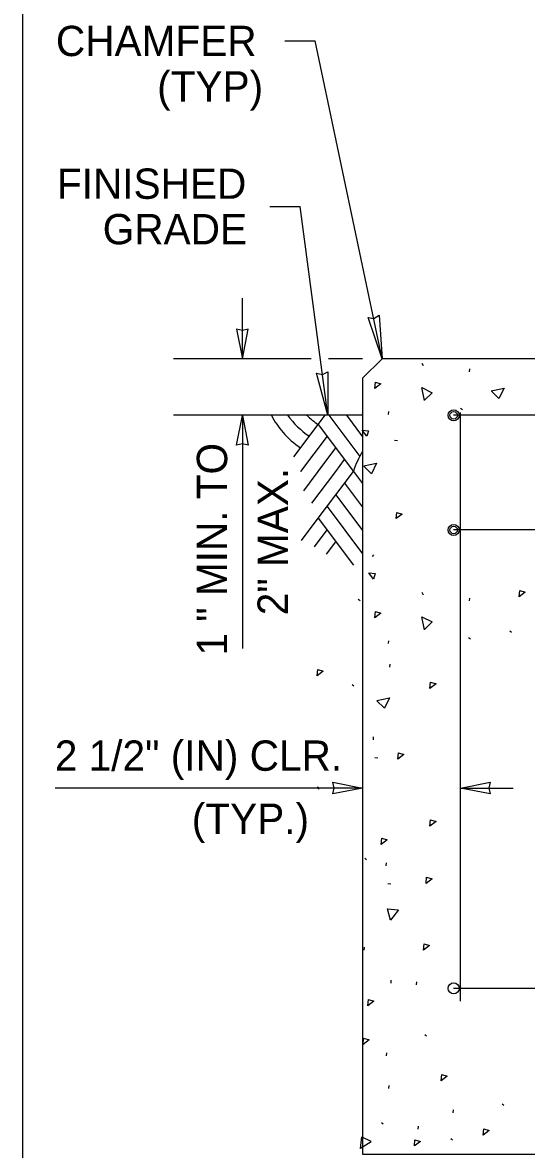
# Model space of a CAD drawing. Extents: x 99862 to 103680, y 99470 to 105076.
# Drawn here: x 99862 to 100128, y 100722 to 101317 of the extents above; entities that cross this region are included whole.
import ezdxf

# ---------------------------------------------------------------- set-up
doc = ezdxf.new("R2010")
doc.units = 0
for name, color, linetype in [('Level 1', 7, 'Continuous'), ('Level 15', 7, 'Continuous'), ('Level 19', 7, 'Continuous'), ('Level 20', 7, 'Continuous'), ('Level 25', 7, 'Continuous'), ('Level 9', 7, 'Continuous')]:
    doc.layers.add(name, color=color, linetype=linetype)

msp = doc.modelspace()

# ---------------------------------------------------------------- linework, layer by layer
at = {"layer": 'Level 1'}
for p, q in [((100051.48, 101139.41), (100041.23, 101129.16)), ((100141.41, 101139.4), (100051.47, 101139.4))]:
    msp.add_line(p, q, dxfattribs=at)
msp.add_lwpolyline([(99862, 99999.5), (103151, 99999.5), (103151, 102075.5), (99862, 102075.5)], close=True, dxfattribs=at)
for points in [[(100041.23, 101129.16), (100041.23, 100934.7)], [(100041.23, 100934.7), (100041.23, 100719.67), (100206.34, 100719.67), (100206.38, 100719.67), (100401.73, 100719.67), (100401.73, 101024.26)]]:
    msp.add_lwpolyline(points, dxfattribs=at)
at = {"layer": 'Level 15'}
for p, q in [((100000.16, 101307.15), (100016.16, 101307.15)), ((100051.47, 101139.4), (100016.16, 101307.15)), ((99992.31, 101219.84), (100008.31, 101219.84)), ((100022.85, 101109.61), (100008.31, 101219.84)), ((99977.84, 101139.4), (99977.84, 101171.4)), ((99995.48, 101109.61), (99958.8, 101109.61)), ((99977.84, 101109.6), (99977.84, 100986.55)), ((100041.23, 100912.91), (99879.13, 100912.91)), ((100092.73, 100912.91), (100120.59, 100912.91))]:
    msp.add_line(p, q, dxfattribs=at)
for points in [[(100051.47, 101139.4), (100044.09, 101161.21), (100047.22, 101160.76), (100049.94, 101162.38)], [(99977.84, 101139.4), (99980.92, 101155.13), (99977.84, 101154.4), (99974.75, 101155.13)], [(100022.85, 101109.61), (100016.95, 101131.86), (100020.04, 101131.2), (100022.87, 101132.63)], [(99977.84, 101109.6), (99980.92, 101093.87), (99977.84, 101094.6), (99974.75, 101093.87)], [(100041.23, 100912.91), (100025.51, 100909.83), (100026.24, 100912.91), (100025.51, 100916)], [(100092.78, 100912.91), (100108.5, 100916), (100107.78, 100912.91), (100108.5, 100909.83)]]:
    msp.add_lwpolyline(points, close=True, dxfattribs=at)
at = {"layer": 'Level 19'}
for p, q in [((100072.45, 101137.17), (100073.09, 101135.87)), ((100097.56, 101132.6), (100097.66, 101134.18)), ((100054.9, 101110.09), (100055.01, 101111.67)), ((100092.86, 101113.35), (100093.79, 101112.67)), ((100058.12, 101096.44), (100059.69, 101096.33)), ((100046.99, 101036.05), (100046.3, 101035.11)), ((100072.45, 101016.21), (100073.09, 101014.91)), ((100038.96, 101012.63), (100039.89, 101011.94)), ((100097.56, 101011.64), (100097.66, 101013.21)), ((100097.09, 100992.39), (100098.02, 100991.71)), ((100118.75, 100995.94), (100119.68, 100995.26)), ((100054.9, 100989.13), (100055.01, 100990.7)), ((100055.61, 100976.66), (100055.72, 100978.24)), ((100035.65, 100967.64), (100036.58, 100966.95)), ((100046.92, 100938.37), (100047.03, 100939.94)), ((100047.7, 100929.02), (100049.28, 100928.91)), ((100017.4, 100913.69), (100018.04, 100912.4)), ((100042.37, 100875.91), (100043.3, 100875.23)), ((100053.68, 100871.89), (100053.79, 100873.46)), ((100054.46, 100862.55), (100056.04, 100862.44)), ((100042.09, 100827.47), (100042.2, 100829.04)), ((100056.22, 100809.97), (100056.33, 100811.54)), ((100069.63, 100809.16), (100069.74, 100810.73)), ((100073.94, 100782.82), (100074.87, 100782.14)), ((100053.79, 100771.68), (100053.91, 100773.26)), ((100055.12, 100754.33), (100055.23, 100755.91)), ((100089.01, 100741.6), (100089.12, 100743.17)), ((100114.8, 100746.35), (100115.73, 100745.66)), ((100051.2, 100736.48), (100052.13, 100735.79)), ((100070.58, 100732.87), (100070.69, 100734.45)), ((100087.69, 100728.05), (100088.62, 100727.36))]:
    msp.add_line(p, q, dxfattribs=at)
for points in [[(100047.72, 101123.76), (100048.04, 101127.07), (100050.92, 101126.2), (100047.72, 101123.76)], [(100073.81, 101117.45), (100072.36, 101124.22), (100077.92, 101121.52), (100073.9, 101117.52)], [(100109.03, 101122.5), (100115.81, 101123.96), (100113.11, 101118.4), (100109.11, 101122.41)], [(100041.03, 101101.77), (100044.34, 101101.44), (100043.47, 101098.57), (100041.03, 101101.77)], [(100041.8, 101082.92), (100048.57, 101084.37), (100045.87, 101078.81), (100041.87, 101082.83)], [(100058.92, 101055.08), (100059.25, 101058.39), (100062.12, 101057.52), (100058.92, 101055.08)], [(100044.48, 101026.42), (100047.79, 101026.09), (100046.92, 101023.22), (100044.48, 101026.42)], [(100123.78, 101013.8), (100124.11, 101017.12), (100126.98, 101016.24), (100123.78, 101013.8)], [(100047.72, 101002.79), (100048.04, 101006.11), (100050.92, 101005.24), (100047.72, 101002.79)], [(100073.81, 100996.48), (100072.36, 101003.26), (100077.92, 101000.56), (100073.9, 100996.56)], [(100017.3, 100972.14), (100017.63, 100975.46), (100020.5, 100974.59), (100017.3, 100972.14)], [(100076.74, 100965.4), (100077.07, 100968.72), (100079.94, 100967.85), (100076.74, 100965.4)], [(100048.69, 100959.11), (100055.46, 100960.56), (100052.76, 100955), (100048.77, 100959.02)], [(100059.76, 100928.13), (100060.08, 100931.45), (100062.96, 100930.57), (100059.76, 100928.13)], [(100076.74, 100892.77), (100077.07, 100896.08), (100079.94, 100895.21), (100076.74, 100892.77)], [(100051.05, 100883.11), (100051.38, 100886.42), (100054.25, 100885.55), (100051.05, 100883.11)], [(100074.66, 100862.54), (100074.99, 100865.85), (100077.86, 100864.98), (100074.66, 100862.54)], [(100060.13, 100848.61), (100055.87, 100843.14), (100054.37, 100849.14), (100060.01, 100848.63)], [(100073.26, 100827.47), (100073.59, 100830.79), (100076.46, 100829.92), (100073.26, 100827.47)], [(100044.03, 100798.06), (100044.36, 100801.37), (100047.23, 100800.5), (100044.03, 100798.06)], [(100041.44, 100777.7), (100041.76, 100781.01), (100044.64, 100780.14), (100041.44, 100777.7)], [(100082.63, 100758.39), (100082.96, 100761.7), (100085.83, 100760.83), (100082.63, 100758.39)], [(100104.81, 100729.71), (100105.14, 100733.03), (100108.01, 100732.16), (100104.81, 100729.71)], [(100045.81, 100726.28), (100040.13, 100722.72), (100040.76, 100728.87), (100045.5, 100726.65)], [(100068.5, 100724.07), (100068.82, 100727.38), (100071.7, 100726.51), (100068.5, 100724.07)]]:
    msp.add_lwpolyline(points, dxfattribs=at)
at = {"layer": 'Level 25'}
for p, q in [((100092.73, 101111.04), (100092.73, 100800.46)), ((100282.03, 101109.61), (100089.22, 101109.61)), ((100282.03, 101049.11), (100089.22, 101049.11)), ((100282.03, 100807.22), (100089.22, 100807.22))]:
    msp.add_line(p, q, dxfattribs=at)
for centre, radius in [((100089.22, 101109.61), 2.92), ((100089.22, 101109.61), 1.95), ((100089.22, 101049.11), 2.92), ((100089.22, 101049.11), 1.95), ((100089.22, 100807.22), 2.92)]:
    msp.add_circle(centre, radius, dxfattribs=at)
at = {"layer": 'Level 9'}
for p, q in [((100014.14, 101139.4), (99941.54, 101139.4)), ((100041.23, 101139.4), (100023.31, 101139.4)), ((100041.3, 101109.61), (99941.6, 101109.61)), ((100012.02, 101109.4), (100012.18, 101109.61)), ((100017.84, 101104.78), (100021.46, 101109.61)), ((100023.5, 101109.61), (100039.74, 101087.95)), ((100032.78, 101109.61), (100041.23, 101098.34)), ((100041.05, 101110.96), (100041.23, 101110.71)), ((100004.98, 101087.63), (100017.84, 101104.78)), ((100017.84, 101104.78), (100036.4, 101080.03)), ((100022.48, 101098.59), (100008.56, 101080.03)), ((100017.84, 101080.03), (100027.12, 101092.41)), ((100027.12, 101080.03), (100031.76, 101086.22)), ((100008.56, 101080.03), (100008.56, 101080.03)), ((100010.19, 101069.84), (100017.84, 101080.03)), ((100014.5, 101063.2), (100027.12, 101080.03)), ((100017.84, 101055.28), (100036.4, 101080.03)), ((100036.4, 101080.03), (100041.23, 101073.59)), ((100031.76, 101073.84), (100041.23, 101061.22)), ((100027.12, 101067.66), (100041.23, 101048.84)), ((100022.48, 101061.47), (100041.23, 101036.47)), ((100008.98, 101043.48), (100017.84, 101055.28)), ((100017.84, 101055.28), (100036.4, 101030.53)), ((100015.81, 101040.2), (100022.48, 101049.1)), ((100022.18, 101036.32), (100027.12, 101042.91))]:
    msp.add_line(p, q, dxfattribs=at)
for centre, start, end in [((100034.76, 101131.39), 207.63272, 220.94161), ((100039.4, 101137.58), 216.54995, 236.09639), ((100044.04, 101143.77), 226.6559, 236.09639), ((100034.76, 101131.39), 220.94154, 236.09639), ((100081.16, 101065.79), 148.22442, 162.3566)]:
    msp.add_arc(centre, 46.97, start, end, dxfattribs=at)

# ---------------------------------------------------------------- texts
at = {"layer": 'Level 20'}
for s, p in [('CHAMFER', (99879.57, 101299.15)), ('(TYP)', (99932.93, 101275.15)), ('FINISHED', (99880.09, 101223.84)), ('GRADE', (99904.24, 101199.84)), ('2 1/2" (IN) CLR.', (99878.99, 100922.05)), ('(TYP.)', (99951.19, 100888.74))]:
    msp.add_text(s, height=16, dxfattribs=at).set_placement(p)
for s, p in [('1 " MIN. TO', (99969.84, 100982.83)), (' 2" MAX.', (100001.84, 100998.19))]:
    msp.add_text(s, height=16, rotation=90, dxfattribs=at).set_placement(p)

doc.saveas('drawing.dxf')
